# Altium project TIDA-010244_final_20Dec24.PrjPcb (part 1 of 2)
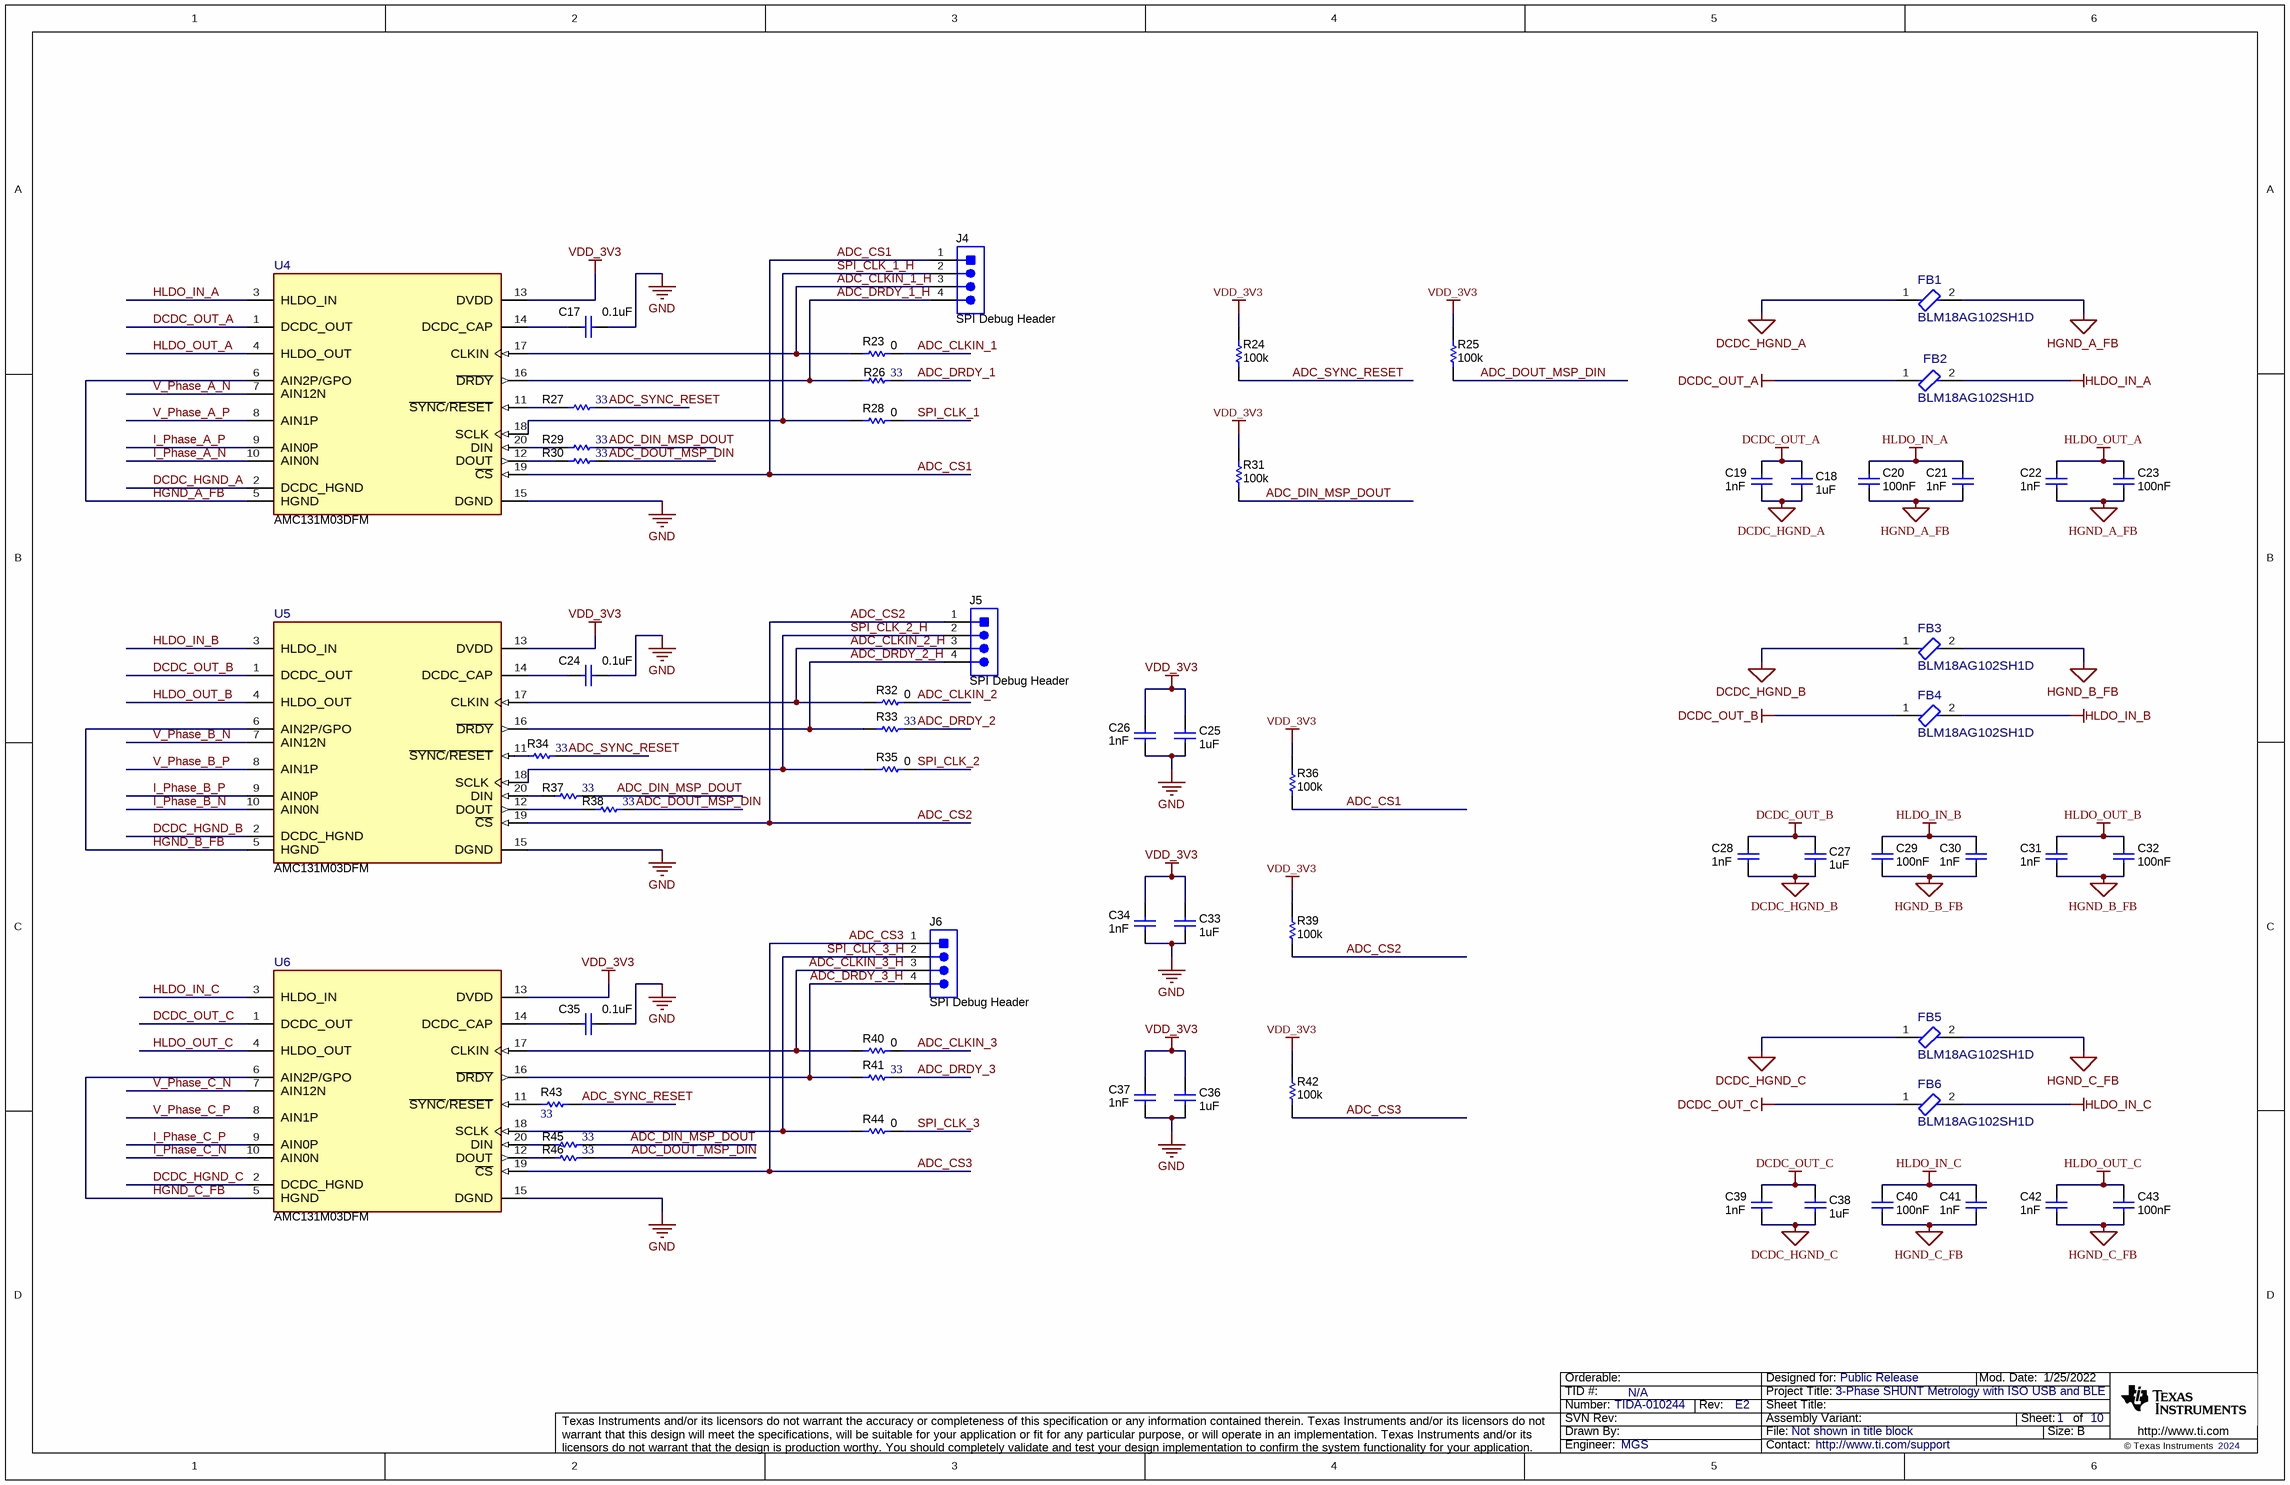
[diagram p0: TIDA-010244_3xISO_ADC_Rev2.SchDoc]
CopyrightYear: 2024; PCB_Layout: a0797195; PCB_Rev: E2; PRJ_Customer: Public Release; PRJ_Engineer: MGS; PRJ_Number: TIDA-010244; PRJ_Title: 3-Phase SHUNT Metrology with ISO USB and BLE; SCH_Rev: E2; TechSupport: http://www.ti.com/support; TID: N/A
9 sheets, 357 parts. Net scope: global (net labels, ports and power ports of the same name join across sheets).
Board file: TIDA-010244_Rev2_final.PcbDoc
Sheets:
  TIDA-010244_3xISO_ADC_Rev2.SchDoc
  TIDA-010244_Hardware.SchDoc
  TIDA-010244_MSPM0G_Rev2.SchDoc
  TIDA-010244_V_I_Filtering_FE_Rev2.SchDoc
  TIDA-010244_USB_and_Power.SchDoc
  TIDA-010244_BLE_Wireless.SchDoc
  TIDA-010244_XDS110_MCU.SchDoc
  TIDA-010244_Neutral_3DHall_Rev2.SchDoc
  TIDA-010244_BLE_Module_HY-2340.SchDoc

## Sheet TIDA-010244_3xISO_ADC_Rev2.SchDoc
size 431 x 279 mm; Date: Not shown in title block; ApprovedBy: Not shown in title block; CheckedBy: Not shown in title block; Author: Not shown in title block; CompanyName: Not shown in title block; Engineer: Not shown in title block; Organization: Not shown in title block; Address1: Not shown in title block; Address2: Not shown in title block; Address3: Not shown in title block; Address4: Not shown in title block; DocumentNumber: 2; Revision: Use project parameter SCH_Rev; SheetNumber: 1; SheetTotal: 10; PageSetup: Record=PageOptions¦CenterHorizontal=True¦CenterVertical=True¦PrintScale=1.00¦XCorrection=1.00¦YCorrection=1.00¦PrintKind=0¦BorderSize=5000000¦LeftOffset=0¦BottomOffset=0¦Orientation=2¦PaperLength=1000¦PaperWidth=1000¦Scale=100¦PaperSource=15¦PrintQuality=600¦MediaType=1¦DitherType=10¦PaperKind=Letter¦PrintScaleMode=1

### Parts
C17  value 0.1uF  [0603]  (hidden comment: C1608X7R1H104K080AA)
C18  ValueDisplayed: 1uF  [0603]  (hidden comment: C0603C105K3RACTU)
C19  Cap_F: 1nF  [0603]  (hidden comment: C0603C102K5RACTU)
C20  Cap_F: 100nF  [0603]  (hidden comment: C1608X7R1H104K080AA)
C21  Cap_F: 1nF  [0603]  (hidden comment: C0603C102K5RACTU)
C22  Cap_F: 1nF  [0603]  (hidden comment: C0603C102K5RACTU)
C23  Cap_F: 100nF  [0603]  (hidden comment: C1608X7R1H104K080AA)
C24  value 0.1uF  [0603]  (hidden comment: C1608X7R1H104K080AA)
C25  ValueDisplayed: 1uF  [0603]  (hidden comment: C0603C105K3RACTU)
C26  Cap_F: 1nF  [0603]  (hidden comment: C0603C102K5RACTU)
C27  ValueDisplayed: 1uF  [0603]  (hidden comment: C0603C105K3RACTU)
C28  Cap_F: 1nF  [0603]  (hidden comment: C0603C102K5RACTU)
C29  Cap_F: 100nF  [0603]  (hidden comment: C1608X7R1H104K080AA)
C30  Cap_F: 1nF  [0603]  (hidden comment: C0603C102K5RACTU)
C31  Cap_F: 1nF  [0603]  (hidden comment: C0603C102K5RACTU)
C32  Cap_F: 100nF  [0603]  (hidden comment: C1608X7R1H104K080AA)
C33  ValueDisplayed: 1uF  [0603]  (hidden comment: C0603C105K3RACTU)
C34  Cap_F: 1nF  [0603]  (hidden comment: C0603C102K5RACTU)
C35  value 0.1uF  [0603]  (hidden comment: C1608X7R1H104K080AA)
C36  ValueDisplayed: 1uF  [0603]  (hidden comment: C0603C105K3RACTU)
C37  Cap_F: 1nF  [0603]  (hidden comment: C0603C102K5RACTU)
C38  ValueDisplayed: 1uF  [0603]  (hidden comment: C0603C105K3RACTU)
C39  Cap_F: 1nF  [0603]  (hidden comment: C0603C102K5RACTU)
C40  Cap_F: 100nF  [0603]  (hidden comment: C1608X7R1H104K080AA)
C41  Cap_F: 1nF  [0603]  (hidden comment: C0603C102K5RACTU)
C42  Cap_F: 1nF  [0603]  (hidden comment: C0603C102K5RACTU)
C43  Cap_F: 100nF  [0603]  (hidden comment: C1608X7R1H104K080AA)
FB1  BLM18AG102SH1D  [FP-BLM18AG102SH1D_0603-MFG]
FB2  BLM18AG102SH1D  [FP-BLM18AG102SH1D_0603-MFG]
FB3  BLM18AG102SH1D  [FP-BLM18AG102SH1D_0603-MFG]
FB4  BLM18AG102SH1D  [FP-BLM18AG102SH1D_0603-MFG]
FB5  BLM18AG102SH1D  [FP-BLM18AG102SH1D_0603-MFG]
FB6  BLM18AG102SH1D  [FP-BLM18AG102SH1D_0603-MFG]
J4  SPI Debug Header  [WURTH_61300411121]
J5  SPI Debug Header  [WURTH_61300411121]
J6  SPI Debug Header  [WURTH_61300411121]
R23  ValueDisplayed: 0  [0603]  (hidden comment: ERJ-3GEY0R00V)
R24  ValueDisplayed: 100k  [0603]  (hidden comment: CRCW0603100KFKEA)
R25  ValueDisplayed: 100k  [0603]  (hidden comment: CRCW0603100KFKEA)
R26  ValueDisplayed: 33  [0603]  (hidden comment: CRCW060333R0JNEA)
R27  ValueDisplayed: 33  [0603]  (hidden comment: CRCW060333R0JNEA)
R28  ValueDisplayed: 0  [0603]  (hidden comment: ERJ-3GEY0R00V)
R29  ValueDisplayed: 33  [0603]  (hidden comment: CRCW060333R0JNEA)
R30  ValueDisplayed: 33  [0603]  (hidden comment: CRCW060333R0JNEA)
R31  ValueDisplayed: 100k  [0603]  (hidden comment: CRCW0603100KFKEA)
R32  ValueDisplayed: 0  [0603]  (hidden comment: ERJ-3GEY0R00V)
R33  ValueDisplayed: 33  [0603]  (hidden comment: CRCW060333R0JNEA)
R34  ValueDisplayed: 33  [0603]  (hidden comment: CRCW060333R0JNEA)
R35  ValueDisplayed: 0  [0603]  (hidden comment: ERJ-3GEY0R00V)
R36  ValueDisplayed: 100k  [0603]  (hidden comment: CRCW0603100KFKEA)
R37  ValueDisplayed: 33  [0603]  (hidden comment: CRCW060333R0JNEA)
R38  ValueDisplayed: 33  [0603]  (hidden comment: CRCW060333R0JNEA)
R39  ValueDisplayed: 100k  [0603]  (hidden comment: CRCW0603100KFKEA)
R40  ValueDisplayed: 0  [0603]  (hidden comment: ERJ-3GEY0R00V)
R41  ValueDisplayed: 33  [0603]  (hidden comment: CRCW060333R0JNEA)
R42  ValueDisplayed: 100k  [0603]  (hidden comment: CRCW0603100KFKEA)
R43  ValueDisplayed: 33  [0603]  (hidden comment: CRCW060333R0JNEA)
R44  ValueDisplayed: 0  [0603]  (hidden comment: ERJ-3GEY0R00V)
R45  ValueDisplayed: 33  [0603]  (hidden comment: CRCW060333R0JNEA)
R46  ValueDisplayed: 33  [0603]  (hidden comment: CRCW060333R0JNEA)
U4  AMC131M03DFM  [DFM0020A-MFG]
U5  AMC131M03DFM  [DFM0020A-MFG]
U6  AMC131M03DFM  [DFM0020A-MFG]

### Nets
DCDC_HGND_A: C18.1 C19.2 FB1.1 U4.2(DCDC_HGND)
DCDC_HGND_B: C27.1 C28.2 FB3.1 U5.2(DCDC_HGND)
DCDC_HGND_C: C38.1 C39.2 FB5.1 U6.2(DCDC_HGND)
DCDC_OUT_A: C18.2 C19.1 FB2.1 U4.1(DCDC_OUT)
DCDC_OUT_B: C27.2 C28.1 FB4.1 U5.1(DCDC_OUT)
DCDC_OUT_C: C38.2 C39.1 FB6.1 U6.1(DCDC_OUT)
GND: C17.2 C24.2 C25.1 C26.2 C33.1 C34.2 C35.2 C36.1 C37.2 U4.15(DGND) U5.15(DGND) U6.15(DGND)
HGND_A_FB: C20.2 C21.2 C22.2 C23.2 FB1.2 U4.5(HGND) U4.6(AIN2P/GPO)
HGND_B_FB: C29.2 C30.2 C31.2 C32.2 FB3.2 U5.5(HGND) U5.6(AIN2P/GPO)
HGND_C_FB: C40.2 C41.2 C42.2 C43.2 FB5.2 U6.5(HGND) U6.6(AIN2P/GPO)
HLDO_IN_A: C20.1 C21.1 FB2.2 U4.3(HLDO_IN)
HLDO_IN_B: C29.1 C30.1 FB4.2 U5.3(HLDO_IN)
HLDO_IN_C: C40.1 C41.1 FB6.2 U6.3(HLDO_IN)
HLDO_OUT_A: C22.1 C23.1 U4.4(HLDO_OUT)
HLDO_OUT_B: C31.1 C32.1 U5.4(HLDO_OUT)
HLDO_OUT_C: C42.1 C43.1 U6.4(HLDO_OUT)
VDD_3V3: C25.2 C26.1 C33.2 C34.1 C36.2 C37.1 R24.2 R25.2 R31.2 R36.2 R39.2 R42.2 U4.13(DVDD) U5.13(DVDD) U6.13(DVDD)
ADC_CLKIN_1: R23.2
ADC_CLKIN_1_H: J4.3 R23.1 U4.17(CLKIN)
ADC_CLKIN_2: R32.2
ADC_CLKIN_2_H: J5.3 R32.1 U5.17(CLKIN)
ADC_CLKIN_3: R40.2
ADC_CLKIN_3_H: J6.3 R40.1 U6.17(CLKIN)
ADC_CS1: J4.1 R36.1 U4.19(~{CS})
ADC_CS2: J5.1 R39.1 U5.19(~{CS})
ADC_CS3: J6.1 R42.1 U6.19(~{CS})
ADC_DIN_MSP_DOUT: R29.2 R31.1 R37.2 R45.2
ADC_DOUT_MSP_DIN: R25.1 R30.2 R38.2 R46.2
ADC_DRDY_1: R26.2
ADC_DRDY_1_H: J4.4 R26.1 U4.16(~{DRDY})
ADC_DRDY_2: R33.2
ADC_DRDY_2_H: J5.4 R33.1 U5.16(~{DRDY})
ADC_DRDY_3: R41.2
ADC_DRDY_3_H: J6.4 R41.1 U6.16(~{DRDY})
ADC_SYNC_RESET: R24.1 R27.2 R34.2 R43.2
I_Phase_A_N: U4.10(AIN0N)
I_Phase_A_P: U4.9(AIN0P)
I_Phase_B_N: U5.10(AIN0N)
I_Phase_B_P: U5.9(AIN0P)
I_Phase_C_N: U6.10(AIN0N)
I_Phase_C_P: U6.9(AIN0P)
SPI_CLK_1: R28.2
SPI_CLK_1_H: J4.2 R28.1 U4.18(SCLK)
SPI_CLK_2: R35.2
SPI_CLK_2_H: J5.2 R35.1 U5.18(SCLK)
SPI_CLK_3: R44.2
SPI_CLK_3_H: J6.2 R44.1 U6.18(SCLK)
V_Phase_A_N: U4.7(AIN12N)
V_Phase_A_P: U4.8(AIN1P)
V_Phase_B_N: U5.7(AIN12N)
V_Phase_B_P: U5.8(AIN1P)
V_Phase_C_N: U6.7(AIN12N)
V_Phase_C_P: U6.8(AIN1P)
NetC17_1: C17.1 U4.14(DCDC_CAP)
NetC24_1: C24.1 U5.14(DCDC_CAP)
NetC35_1: C35.1 U6.14(DCDC_CAP)
NetR27_1: R27.1 U4.11(~{SYNC}/~{RESET})
NetR29_1: R29.1 U4.20(DIN)
NetR30_1: R30.1 U4.12(DOUT)
NetR34_1: R34.1 U5.11(~{SYNC}/~{RESET})
NetR37_1: R37.1 U5.20(DIN)
NetR38_1: R38.1 U5.12(DOUT)
NetR43_1: R43.1 U6.11(~{SYNC}/~{RESET})
NetR45_1: R45.1 U6.20(DIN)
NetR46_1: R46.1 U6.12(DOUT)

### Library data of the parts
C17 C24 C35 = CMP-0007044-5: CAP, CERM, 0.1 uF, 50 V, +/- 10%, X7R, 0603; Manufacturer: TDK; TaMin_C: -55°C; ESR_ohm: 29.6m; Polarized: N; SizeAreaWB_mm2: 4.68; Value1: 0.0296 ohm; U/M: EA; TaMax_C: 125°C; SizeZ_mm: 1; SizeX_mm: 1.6; SizeY_mm: 0.8; Value2: 50V; SizeArea_mm2: 1.28; IRMS_A: 971.99mA; AEC Category: Q200
C18 C25 C27 C33 C36 C38 = CMP-0006867-4: CAP, CERM, 1 uF, 25 V, +/- 10%, X7R, 0603; Manufacturer: Kemet; TaMin_C: -55°C; Polarized: N; SizeAreaWB_mm2: 4.68; Value1: Unknown; U/M: EA; Value: 1uF; TaMax_C: 125°C; SizeZ_mm: 1; SizeX_mm: 1.6; SizeY_mm: 0.8; Value2: 25V; SizeArea_mm2: 1.28; CompType: Capacitor; Cap_F: 1µF; AEC Category: Q200
C19 C21 C22 C26 C28 C30 C31 C34 C37 C39 C41 C42 = CMP-0006847-4: CAP, CERM, 1000 pF, 50 V, +/- 10%, X7R, 0603; Manufacturer: Kemet; TaMin_C: -55°C; Polarized: N; SizeAreaWB_mm2: 4.68; Value1: Unknown; U/M: EA; Value: 1000pF; TaMax_C: 125°C; SizeZ_mm: 1; SizeX_mm: 1.6; SizeY_mm: 0.8; Value2: 50V; SizeArea_mm2: 1.28; AEC Category: Q200
C20 C23 C29 C32 C40 C43 = CMP-0007044-5: CAP, CERM, 0.1 uF, 50 V, +/- 10%, X7R, 0603; Manufacturer: TDK; TaMin_C: -55°C; ESR_ohm: 29.6m; Polarized: N; SizeAreaWB_mm2: 4.68; Value1: 0.0296 ohm; U/M: EA; Value: 0.1uF; TaMax_C: 125°C; SizeZ_mm: 1; SizeX_mm: 1.6; SizeY_mm: 0.8; Value2: 50V; SizeArea_mm2: 1.28; IRMS_A: 971.99mA; AEC Category: Q200
FB1-FB6 = CMP-0092964-1: Chip Ferrite Bead, 0603, 1000Ω @ 100MHz, 0.5Ω, 25%, 450mA; Manufacturer: Murata; SizeZ_mm: 0.95mm; AEC Qualified: Yes; DCR_ohm: 0.5; AEC Grade: Grade 1
J4-J6 = CMP-0054798-2: Header, 2.54 mm, 4x1, Gold, TH; Manufacturer: Wurth Elektronik; PartNumber: 61300411121; Pitch_mm: 2.54; Gender: Male; Row_Count: 1; Cert_UL: Y; Shrouded: N
R23 R28 R32 R35 R40 R44 = CMP-0025874-4: RES, 0, 5%, 0.1 W, AEC-Q200 Grade 0, 0603; Manufacturer: Panasonic; Power_W: 100mW; TempCo: 600 ppm/C; Value_Code: 0000; Value: 0; EIA_Code: E24; SizeX_mm: 1.6; SizeY_mm: 0.8; SizeZ_mm: 1; Value2: 0.1W; SizeArea_mm2: 1.28; AEC Qualified: Y; VDC_V: 50V; AEC Category: Q200; SizeAreaWB_mm2: 4.68
R24 R25 R31 R36 R39 R42 = CMP-0021990-4: RES, 100 k, 1%, 0.1 W, AEC-Q200 Grade 0, 0603; Manufacturer: Vishay-Dale; Power_W: 100mW; TempCo: 100 ppm/C; Value: 100k; EIA_Code: E96; SizeX_mm: 1.6; SizeY_mm: 0.8; SizeZ_mm: 1; Value2: 0.1W; SizeArea_mm2: 1.28; AEC Qualified: Y; VDC_V: 75V; AEC Category: Q200; AEC Grade: 0
R26 R27 R29 R30 R33 R34 R37 R38 R41 R43 R45 R46 = CMP-0025787-4: RES, 33, 5%, 0.1 W, AEC-Q200 Grade 0, 0603; Manufacturer: Vishay-Dale; Power_W: 100mW; TempCo: 200 ppm/C; Value_Code: 33R0; Value: 33; EIA_Code: E24; SizeX_mm: 1.6; SizeY_mm: 0.8; SizeZ_mm: 1; Value2: 0.1W; SizeArea_mm2: 1.28; AEC Qualified: Y; VDC_V: 75V; AEC Category: Q200; AEC Grade: 0
U4-U6 = CMP-0093943-1: 3-Channel, Simultaneously-Sampling, 24-Bit, Reinforced Isolated DeltaSigma ADC With Integrated DC/DC Converter; Manufacturer: Texas Instruments; Interface: SPI; TaMax_C: +125°C; Standoff Height: 0.1mm; Resolution: 24bits; Max Supply Voltage: 5.5V; Data Polarity: Differential; Min Supply Voltage: 3V; TJmax_C: +150°C; Number Of Channels: 3; Sampling Rate: 32ksps; TaMin_C: -40°C; SizeZ_mm: 3.55mm; AEC Qualified: No

## Sheet TIDA-010244_Hardware.SchDoc
size 431 x 279 mm; Date: Not shown in title block; ApprovedBy: Not shown in title block; CheckedBy: Not shown in title block; Author: Not shown in title block; CompanyName: Not shown in title block; Engineer: Not shown in title block; Organization: Not shown in title block; Address1: Not shown in title block; Address2: Not shown in title block; Address3: Not shown in title block; Address4: Not shown in title block; DocumentNumber: 3; Revision: Use project parameter SCH_Rev; SheetNumber: 2; SheetTotal: 9; PageSetup: Record=PageOptions¦CenterHorizontal=True¦CenterVertical=True¦PrintScale=1.00¦XCorrection=1.00¦YCorrection=1.00¦PrintKind=0¦BorderSize=5000000¦LeftOffset=0¦BottomOffset=0¦Orientation=2¦PaperLength=1000¦PaperWidth=1000¦Scale=100¦PaperSource=15¦PrintQuality=600¦MediaType=1¦DitherType=10¦PaperKind=Letter¦PrintScaleMode=1
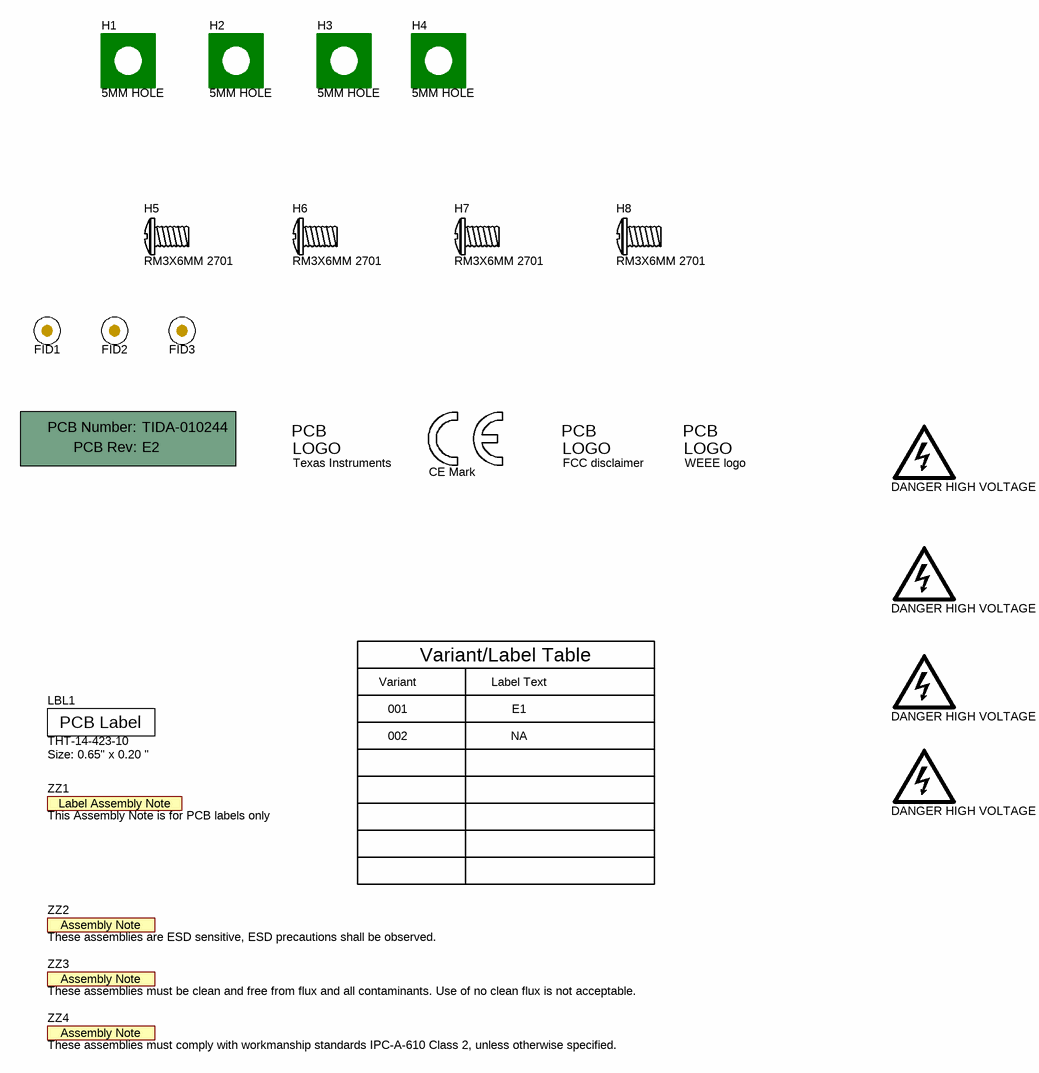
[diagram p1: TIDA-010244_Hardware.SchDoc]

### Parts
!PCB1  Printed Circuit Board  (value not drawn)  (mechanical)
FID1  Fiducial  [Fiducial10-20]  (value not drawn)
FID2  Fiducial  [Fiducial10-20]  (value not drawn)
FID3  Fiducial  [Fiducial10-20]  (value not drawn)
H1  5MM HOLE  [5MM_HOLE]
H2  5MM HOLE  [5MM_HOLE]
H3  5MM HOLE  [5MM_HOLE]
H4  5MM HOLE  [5MM_HOLE]
H5  RM3X6MM 2701  (mechanical)
H6  RM3X6MM 2701  (mechanical)
H7  RM3X6MM 2701  (mechanical)
H8  RM3X6MM 2701  (mechanical)
LBL1  THT-14-423-10  Note: Size: 0.65" x 0.20 "  [Label_650x200]
Logo1  Texas Instruments  [TI_Stacked_Overlay_Small]  (no BOM)
Logo2  CE Mark  [CE_Mark_5mm]  (no BOM)
Logo3  FCC disclaimer  [FCC_disclaimer]  (no BOM)
Logo4  WEEE logo  [WEEE_Minimum]  (no BOM)
LOGO5  DANGER HIGH VOLTAGE  [IEC_HighVoltage_Medium]  (no BOM)
LOGO6  DANGER HIGH VOLTAGE  [IEC_HighVoltage_Medium]  (no BOM)
LOGO7  DANGER HIGH VOLTAGE  [IEC_HighVoltage_Medium]  (no BOM)
LOGO8  DANGER HIGH VOLTAGE  [IEC_HighVoltage_Medium]  (no BOM)
ZZ1  This Assembly Note is for PCB labels only  [AssemblyNoteLabel]  (no BOM)
ZZ2  These assemblies are ESD sensitive, ESD precautions shall be observed.  [AssemblyNote]  (no BOM)
ZZ3  These assemblies must be clean and free from flux and all contaminants. Use of no clean flux is not acceptable.  [AssemblyNote]  (no BOM)
ZZ4  These assemblies must comply with workmanship standards IPC-A-610 Class 2, unless otherwise specified.  [AssemblyNote]  (no BOM)

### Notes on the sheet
- Variant
- Variant/Label Table
- Label Text
- 001
- 002
- E1
- NA

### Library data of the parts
!PCB1 = CMP-0003618-2: Manufacturer: Any; PartNumber: TIDA-010244
FID1-FID3 = CMP-0077181-1: Fiducial mark.  There is nothing to buy or mount.
H1-H4 = CMP-0079337-1: 5 mm PCB Hole; Manufacturer: Any; CompType: Pad
H5-H8 = CMP-0077936-1: MACHINE SCREW PAN PHILLIPS M3; Manufacturer: APM HEXSEAL; CompType: Standoff
LBL1 = CMP-0003625-1: Thermal Transfer Printable Labels, 0.650" W x 0.200" H - 10,000 per roll; Manufacturer: Brady; CompType: Label
Logo1 = CMP-0074838-1: Texas Instrument Corporate Signature; SymbolCreator: a0412235; Lib Reference: TI_Logo; Library Reference: Logo
Logo2 = CMP-0074844-1: SymbolCreator: a0412235
Logo3 = CMP-0074847-1: FCC_disclaimer; Library Reference: Logo
Logo4 = CMP-0074769-1
LOGO5-LOGO8 = CMP-0074835-1: IEC 61010-1 High Voltage Warning; SymbolCreator: a0412235
ZZ1 = CMP-0003616-3
ZZ2 = CMP-0077236-1
ZZ3 = CMP-0077237-1
ZZ4 = CMP-0077238-1

## Sheet TIDA-010244_MSPM0G_Rev2.SchDoc
size A2; Date: Not shown in title block; ApprovedBy: Not shown in title block; CheckedBy: Not shown in title block; Author: Not shown in title block; CompanyName: Not shown in title block; Engineer: Not shown in title block; Organization: Not shown in title block; Address1: Not shown in title block; Address2: Not shown in title block; Address3: Not shown in title block; Address4: Not shown in title block; DocumentNumber: 1; Revision: Use project parameter SCH_Rev; SheetNumber: 3; SheetTotal: 9; PageSetup: Record=PageOptions¦CenterHorizontal=True¦CenterVertical=True¦PrintScale=0.69¦XCorrection=1.00¦YCorrection=1.00¦PrintKind=0¦BorderSize=5000000¦LeftOffset=0¦BottomOffset=0¦Orientation=2¦PaperLength=1000¦PaperWidth=1000¦Scale=100¦PaperSource=15¦PrintQuality=600¦MediaType=1¦DitherType=10¦PaperKind=Letter¦PrintScaleMode=1
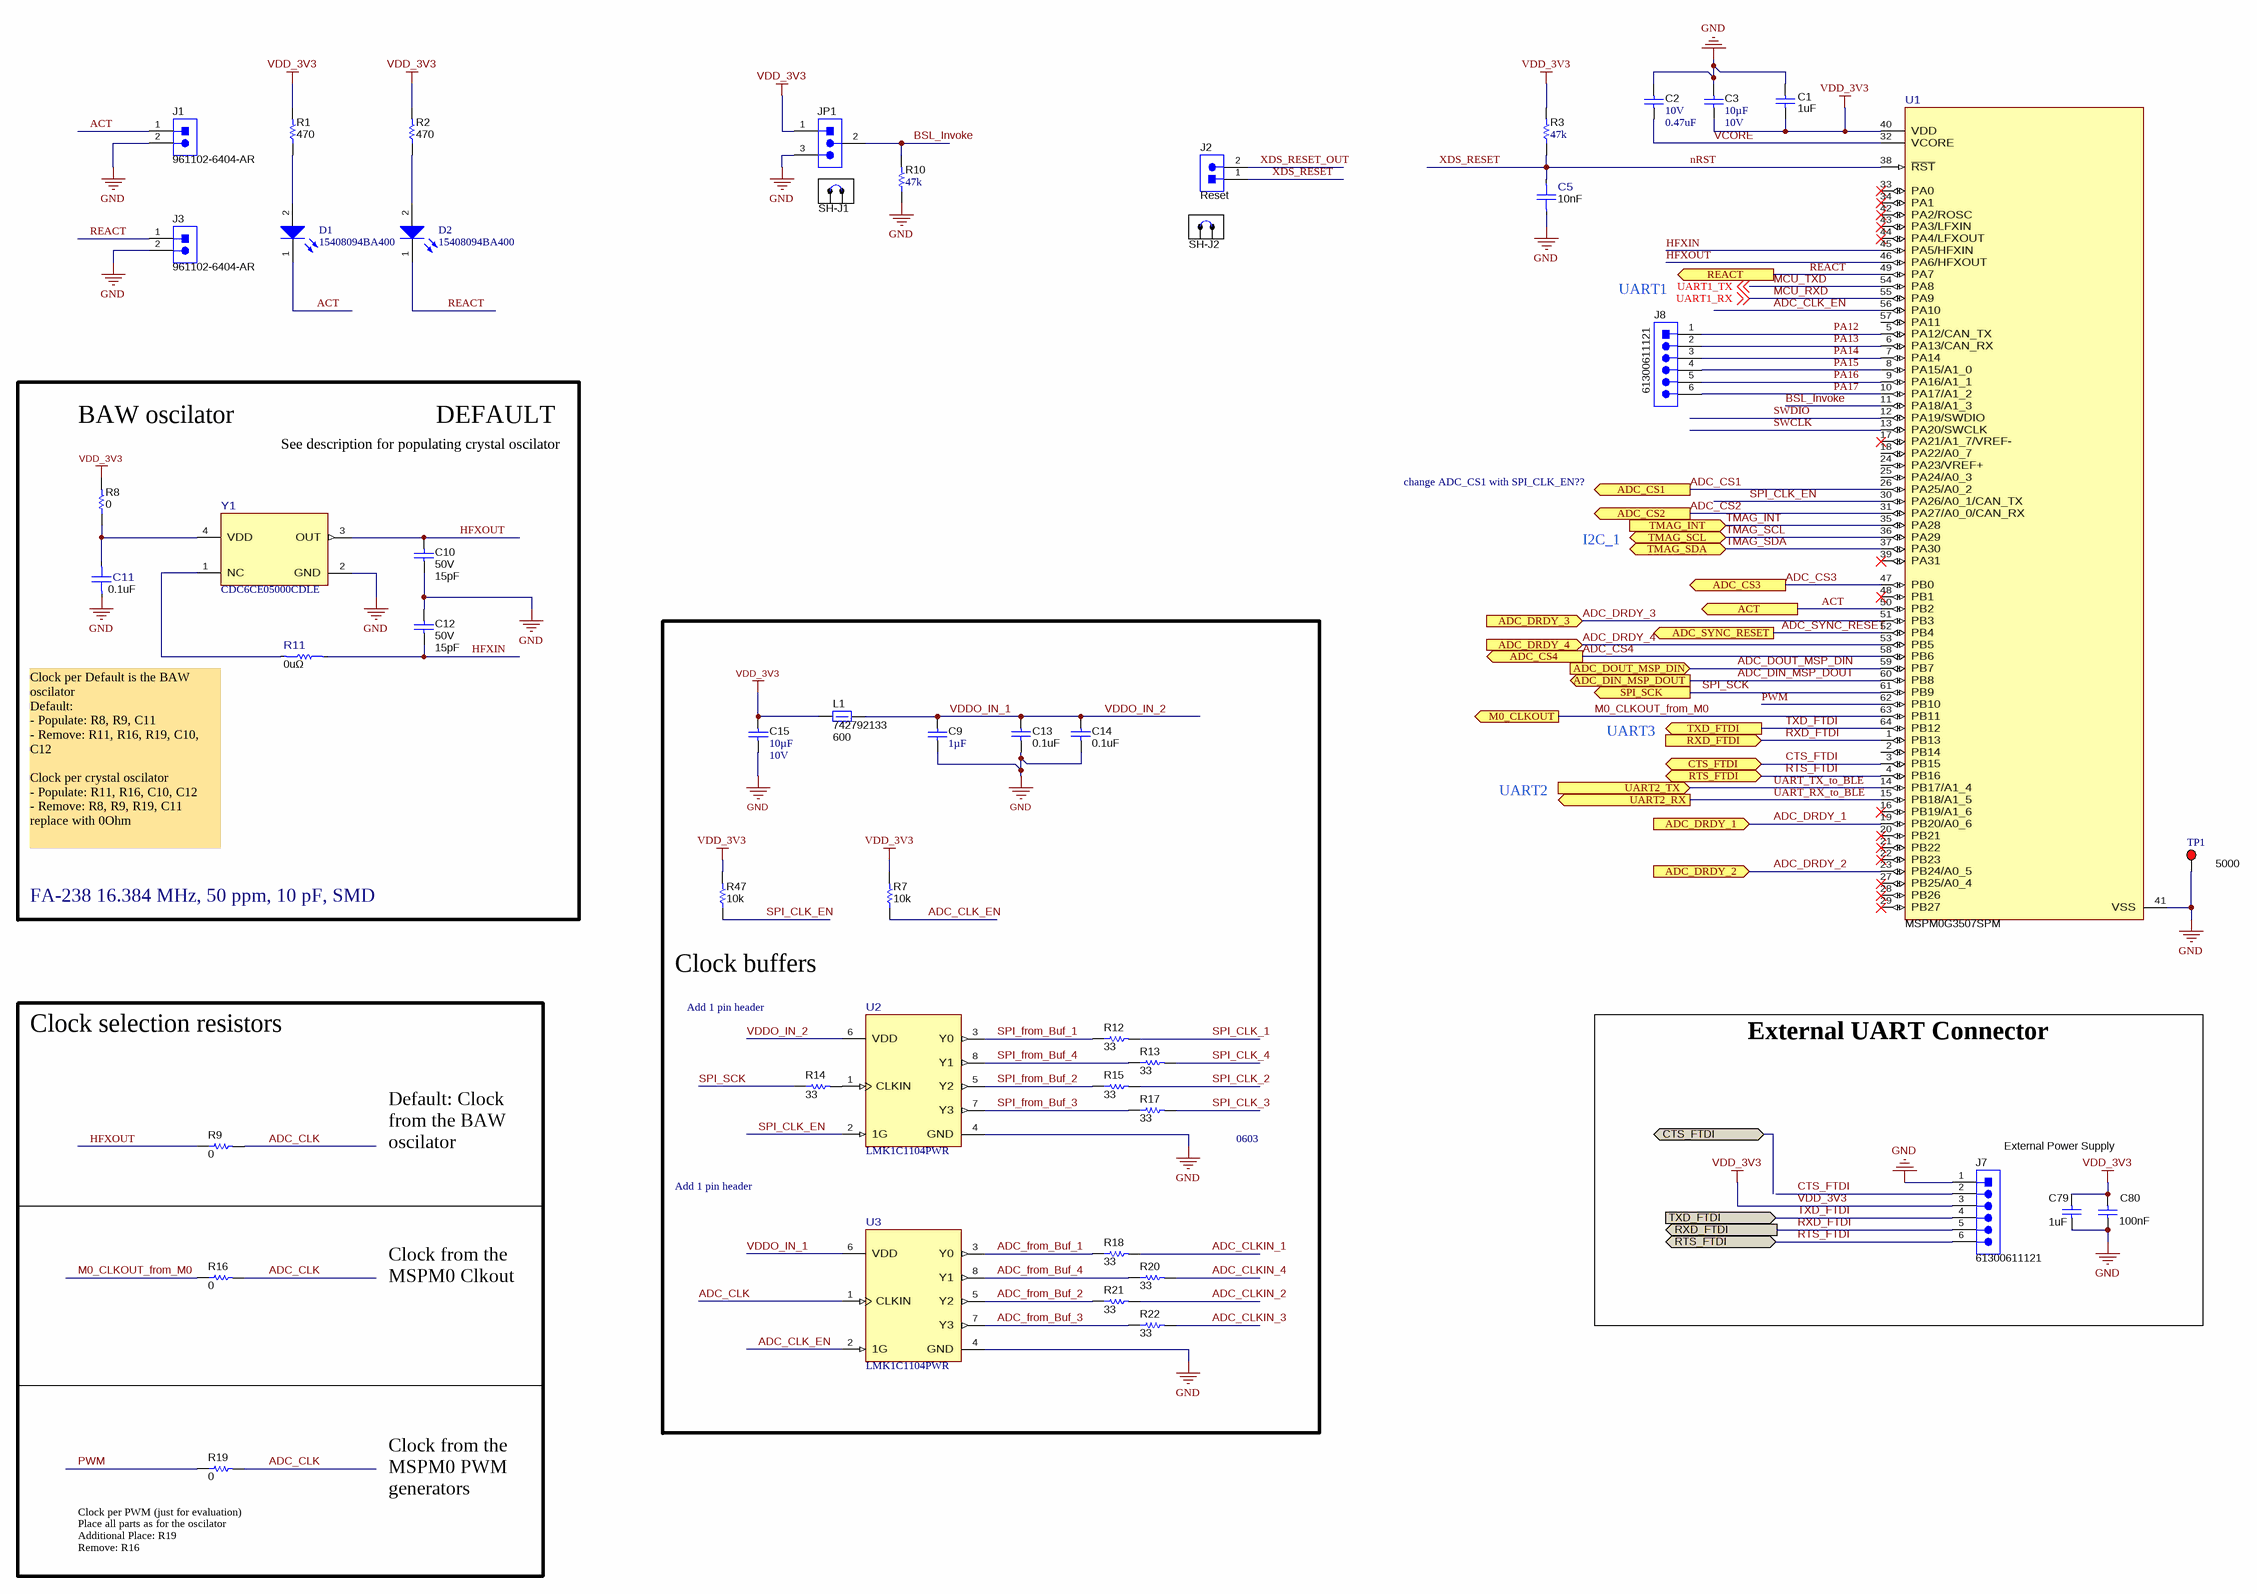
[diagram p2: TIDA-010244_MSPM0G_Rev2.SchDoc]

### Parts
C1  ValueDisplayed: 1uF  [0603]  (hidden comment: C0603C105K3RACTU)
C2  VDC_V: 10V  ValueDisplayed: 0.47uF  [0603]  (hidden comment: GRM188R61A474KA61D)
C3  ValueDisplayed: 10µF  VDC_V: 10V  [0603]  (hidden comment: GRM188R61A106KAALD)
C5  ValueDisplayed: 10nF  [FP-885012205050_0402-MFG]  (hidden comment: 885012205050)
C9  Cap_F: 1µF  [0603]  (hidden comment: CGA3E1X7R1C105K080AC)
C10  VDC_V: 50V  ValueDisplayed: 15pF  [0402]  (hidden comment: GRM1555C1H150JA01D)
C11  ValueDisplayed: 0.1uF  [FP-885012205018_0402-MFG]  (hidden comment: 885012205018)
C12  VDC_V: 50V  ValueDisplayed: 15pF  [0402]  (hidden comment: GRM1555C1H150JA01D)
C13  value 0.1uF  [0603]  (hidden comment: C1608X7R1H104K080AA)
C14  value 0.1uF  [0603]  (hidden comment: C1608X7R1H104K080AA)
C15  ValueDisplayed: 10µF  VDC_V: 10V  [0603]  (hidden comment: GRM188R61A106KAALD)
C79  ValueDisplayed: 1uF  [0603]  (hidden comment: C0603C105K3RACTU)
C80  Cap_F: 100nF  [0603]  (hidden comment: C0603X104K3RACTU)
D1  15408094BA400  [WL-SICW_0805_L2W1.3H0.8]
D2  15408094BA400  [WL-SICW_0805_L2W1.3H0.8]
J1  961102-6404-AR  [3M_961102-6404-AR]
J2  Reset  [3M_961102-6404-AR]
J3  961102-6404-AR  [3M_961102-6404-AR]
J7  61300611121  [WURTH_61300611121]
J8  61300611121  [WURTH_61300611121]
JP1  TSW-103-07-G-S  [TSW-103-07-G-S]  (value not drawn)
L1  742792133  ZTyp@100MHz_Ohm: 600  [1206]
R1  ValueDisplayed: 470  [0402]  (hidden comment: RC0402FR-07470RL)
R2  ValueDisplayed: 470  [0402]  (hidden comment: RC0402FR-07470RL)
R3  ValueDisplayed: 47k  [0402]  (hidden comment: CRCW040247K0JNED)
R7  ValueDisplayed: 10k  [0402]  (hidden comment: CRCW040210K0JNED)
R8  ValueDisplayed: 0  [0402]  (hidden comment: RC0402JR-070RL)
R9  ValueDisplayed: 0  [0603]  (hidden comment: ERJ-3GEY0R00V)
R10  ValueDisplayed: 47k  [0402]  (hidden comment: CRCW040247K0JNED)
R11  value 0uΩ  [FP-CR0402-10W-000T_0402-MFG]  (hidden comment: CR0402-10W-000T)
R12  ValueDisplayed: 33  [0402]  (hidden comment: CRCW040233R0JNED)
R13  ValueDisplayed: 33  [0402]  (hidden comment: CRCW040233R0JNED)
R14  ValueDisplayed: 33  [0402]  (hidden comment: CRCW040233R0JNED)
R15  ValueDisplayed: 33  [0402]  (hidden comment: CRCW040233R0JNED)
R16  ValueDisplayed: 0  [0603]  (hidden comment: ERJ-3GEY0R00V)
R17  ValueDisplayed: 33  [0402]  (hidden comment: CRCW040233R0JNED)
R18  ValueDisplayed: 33  [0402]  (hidden comment: CRCW040233R0JNED)
R19  ValueDisplayed: 0  [0603]  (hidden comment: ERJ-3GEY0R00V)
R20  ValueDisplayed: 33  [0402]  (hidden comment: CRCW040233R0JNED)
R21  ValueDisplayed: 33  [0402]  (hidden comment: CRCW040233R0JNED)
R22  ValueDisplayed: 33  [0402]  (hidden comment: CRCW040233R0JNED)
R47  ValueDisplayed: 10k  [0402]  (hidden comment: CRCW040210K0JNED)
SH-J1  881545-2  [TE_881545-2]  (value not drawn)  (mechanical)
SH-J2  881545-2  [TE_881545-2]  (value not drawn)  (mechanical)
TP1  5000  [Keystone5000]
U1  MSPM0G3507SPM  [PM0064A-MFG]
U2  LMK1C1104PWR  [PW0008A-MFG]
U3  LMK1C1104PWR  [PW0008A-MFG]
Y1  CDC6CE05000CDLE  [DLE0004A-MFG]

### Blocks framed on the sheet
Clock buffers: C9 C13-C15 L1 R7 R12-R15 R17 R18 R20-R22 R47 U2 U3
Clock selection resistors: R9 R16 R19

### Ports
ACT (out), ADC_CS1 (out), ADC_CS2 (out), ADC_CS3 (out), ADC_CS4 (out), ADC_DIN_MSP_DOUT (out), ADC_DOUT_MSP_DIN (in), ADC_DRDY_1 (in), ADC_DRDY_2 (in), ADC_DRDY_3 (in), ADC_DRDY_4 (in), ADC_SYNC_RESET (out), CTS_FTDI (bidir), M0_CLKOUT (out), REACT (out), RTS_FTDI (bidir), RXD_FTDI (in), RXD_FTDI (out), SPI_SCK (out), TMAG_INT (in), TMAG_SCL (bidir), TMAG_SDA (bidir), TXD_FTDI (in), TXD_FTDI (out), UART2_RX (out), UART2_TX (in)

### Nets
GND: C1.2 C2.1 C3.1 C5.1 C9.2 C10.2 C11.1 C12.1 C13.1 C14.1 C15.2 C79.1 C80.2 J1.2 J3.2 J7.1 JP1.3 R10.1 TP1.1 U1.41(VSS) U2.4(GND) U3.4(GND) Y1.2(GND)
VDD_3V3: C1.1 C3.2 C15.1 C79.2 C80.1 J7.3 JP1.1 L1.1 R1.2 R2.2 R3.2 R7.2 R8.2 R47.2 U1.40(VDD)
ACT: D1.1(K) J1.1 U1.50(PB2) ; port ACT
ADC_CLK: R9.2 R16.2 R19.2 U3.1(CLKIN)
ADC_CLK_EN: R7.1 U1.56(PA10) U3.2(1G)
ADC_CLKIN_1: R18.2
ADC_CLKIN_2: R21.2
ADC_CLKIN_3: R22.2
ADC_CLKIN_4: R20.2
ADC_CS1: U1.26(PA25/A0_2) ; port ADC_CS1
ADC_CS2: U1.31(PA27/A0_0/CAN_RX) ; port ADC_CS2
ADC_CS3: U1.47(PB0) ; port ADC_CS3
ADC_CS4: U1.58(PB6) ; port ADC_CS4
ADC_DIN_MSP_DOUT: U1.60(PB8) ; port ADC_DIN_MSP_DOUT
ADC_DOUT_MSP_DIN: U1.59(PB7) ; port ADC_DOUT_MSP_DIN
ADC_DRDY_1: U1.19(PB20/A0_6) ; port ADC_DRDY_1
ADC_DRDY_2: U1.23(PB24/A0_5) ; port ADC_DRDY_2
ADC_DRDY_3: U1.51(PB3) ; port ADC_DRDY_3
ADC_DRDY_4: U1.53(PB5) ; port ADC_DRDY_4
ADC_from_Buf_1: R18.1 U3.3(Y0)
ADC_from_Buf_2: R21.1 U3.5(Y2)
ADC_from_Buf_3: R22.1 U3.7(Y3)
ADC_from_Buf_4: R20.1 U3.8(Y1)
ADC_SYNC_RESET: U1.52(PB4) ; port ADC_SYNC_RESET
BSL_Invoke: JP1.2 R10.2 U1.11(PA18/A1_3)
CTS_FTDI: J7.2 U1.3(PB15) ; port CTS_FTDI
HFXIN: C12.2 R11.2 U1.45(PA5/HFXIN)
HFXOUT: C10.1 R9.1 U1.46(PA6/HFXOUT) Y1.3(OUT)
M0_CLKOUT_from_M0: R16.1 U1.63(PB11) ; port M0_CLKOUT
MCU_RXD: U1.55(PA9) ; off-sheet UART1_RX  [also labelled UART1_RX]
MCU_TXD: U1.54(PA8) ; off-sheet UART1_TX  [also labelled UART1_TX]
nRST: C5.2 J2.1 R3.1 U1.38(~{RST})  [also labelled XDS_RESET]  [project net CC_RESET]
PA12: J8.1 U1.5(PA12/CAN_TX)
PA13: J8.2 U1.6(PA13/CAN_RX)
PA14: J8.3 U1.7(PA14)
PA15: J8.4 U1.8(PA15/A1_0)
PA16: J8.5 U1.9(PA16/A1_1)
PA17: J8.6 U1.10(PA17/A1_2)
PWM: R19.1 U1.62(PB10)
REACT: D2.1(K) J3.1 U1.49(PA7) ; port REACT
RTS_FTDI: J7.6 U1.4(PB16) ; port RTS_FTDI
RXD_FTDI: J7.5 U1.1(PB13) ; port RXD_FTDI
SPI_CLK_1: R12.2
SPI_CLK_2: R15.2
SPI_CLK_3: R17.2
SPI_CLK_4: R13.2
SPI_CLK_EN: R47.1 U1.30(PA26/A0_1/CAN_TX) U2.2(1G)
SPI_from_Buf_1: R12.1 U2.3(Y0)
SPI_from_Buf_2: R15.1 U2.5(Y2)
SPI_from_Buf_3: R17.1 U2.7(Y3)
SPI_from_Buf_4: R13.1 U2.8(Y1)
SPI_SCK: R14.1 U1.61(PB9) ; port SPI_SCK
SWCLK: U1.13(PA20/SWCLK)
SWDIO: U1.12(PA19/SWDIO)
TMAG_INT: U1.35(PA28) ; port TMAG_INT
TMAG_SCL: U1.36(PA29) ; port TMAG_SCL
TMAG_SDA: U1.37(PA30) ; port TMAG_SDA
TXD_FTDI: J7.4 U1.64(PB12) ; port TXD_FTDI
UART_RX_to_BLE: U1.15(PB18/A1_5) ; port UART2_RX
UART_TX_to_BLE: U1.14(PB17/A1_4) ; port UART2_TX
VCORE: C2.2 U1.32(VCORE)
VDDO_IN_1: C9.1 C13.2 C14.2 L1.2 U2.6(VDD) U3.6(VDD)  [also labelled VDDO_IN_2]
XDS_RESET_OUT: J2.2
NetC11_2: C11.2 R8.1 Y1.4(VDD)
NetD1_2: D1.2(A) R1.1
NetD2_2: D2.2(A) R2.1
NetR11_1: R11.1 Y1.1(NC)
NetR14_2: R14.2 U2.1(CLKIN)

Not connected (* = marked no-connect by the designer): U1 2(PB14) 16(PB19/A1_6)* 17(PA21/A1_7/VREF-)* 18(PA22/A0_7) 20(PB21)* 21(PB22)* 22(PB23)* 24(PA23/VREF+) 25(PA24/A0_3) 27(PB25/A0_4)* 28(PB26)* 29(PB27)* 33(PA0)* 34(PA1)* 39(PA31)* 42(PA2/ROSC)* 43(PA3/LFXIN)* 44(PA4/LFXOUT)* 48(PB1)* 57(PA11)

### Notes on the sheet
- (near J8) UART1
- BAW oscilator
- See description for populating crystal oscilator
- DEFAULT
- change ADC_CS1 with SPI_CLK_EN??
- I2C_1
- UART3
- UART2
- Clock per Default is the BAW oscilator
  Default:
  - Populate: R8, R9, C11
  - Remove: R11, R16, R19, C10, C12
  Clock per crystal oscilator
  - Populate: R11, R16, C10, C12
  - Remove: R8, R9, R19, C11 replace with 0Ohm
- FA-238 16.384 MHz, 50 ppm, 10 pF, SMD
- Add 1 pin header
- 0603
- External Power Supply
- Default: Clock from the BAW oscilator
- Clock from the MSPM0 Clkout
- External UART Connector
- (near R19) Clock per PWM (just for evaluation)
  Place all parts as for the oscilator
  Additional Place: R19
  Remove: R16
- Clock from the MSPM0 PWM generators

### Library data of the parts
C1 C79 = CMP-0006867-4: as C18 on sheet TIDA-010244_3xISO_ADC_Rev2
C2 = CMP-0007328-5: CAP, CERM, 0.47 uF, 10 V, +/- 10%, X5R, 0603; Manufacturer: MuRata; TaMin_C: -55°C; Polarized: N; SizeAreaWB_mm2: 4.68; Value1: Unknown; U/M: EA; Value: 0.47uF; TaMax_C: 85°C; SizeZ_mm: 1; SizeX_mm: 1.6; SizeY_mm: 0.8; SizeArea_mm2: 1.28; Cap_F: 470nF; AEC Category: Q200
C3 C15 = CMP-0086193-1: CAP, CERM, 10 µF, 10 V,+/- 10%, X5R, 0603; Manufacturer: MuRata; SizeArea_mm2: 1.28; SizeY_mm: 0.8; TaMax_C: 85°C; TaMin_C: -55°C; Polarized: N; SizeAreaWB_mm2: 4.68; SizeZ_mm: 1; SizeX_mm: 1.6; AEC Category: Q200; U/M: EA; Value: 10uF
C5 = CMP-0090363-1: 10000pF ±10% 25V Ceramic Capacitor X7R 0402 (1005 Metric); Manufacturer: Wurth Electronics; SizeZ_mm: 0.55mm; AEC Qualified: No; Value: 10nF; TempCo: 15%
C9 = CMP-0079607-1: CAP, CERM, 1 µF, 16 V,+/- 10%, X7R, AEC-Q200 Grade 1, 0603; Manufacturer: TDK; TaMin_C: -55°C; Polarized: N; SizeAreaWB_mm2: 4.68; U/M: EA; Value: 1uF; TaMax_C: 125°C; SizeZ_mm: 1; SizeX_mm: 1.6; SizeY_mm: 0.8; Value2: 16V; SizeArea_mm2: 1.28; AEC Qualified: Y; AEC Category: Q200
C10 C12 = CMP-0006420-2: CAP, CERM, 15 pF, 50 V, +/- 5%, C0G/NP0, 0402; Manufacturer: MuRata; TaMin_C: -55°C; Polarized: N; SizeAreaWB_mm2: 3; Value1: Unknown; U/M: EA; Value: 15pF; TaMax_C: 125°C; SizeZ_mm: 0.6; SizeX_mm: 1; SizeY_mm: 0.5; AEC Category: Q200
C11 = CMP-0090362-1: 0.1µF ±10% 10V Ceramic Capacitor X7R 0402 (1005 Metric); Manufacturer: Wurth Electronics; AEC Qualified: No; Value: 100nF; SizeZ_mm: 0.55mm; TempCo: 15%
C13 C14 = CMP-0007044-5: as C17 on sheet TIDA-010244_3xISO_ADC_Rev2
C80 = CMP-0006979-5: CAP, CERM, 0.1 uF, 25 V, +/- 10%, X7R, 0603; Manufacturer: Kemet; TaMin_C: -55°C; Polarized: N; SizeAreaWB_mm2: 4.68; Value1: Unknown; U/M: EA; Value: 0.1uF; TaMax_C: 125°C; SizeZ_mm: 1; SizeX_mm: 1.6; SizeY_mm: 0.8; Value2: 25V; SizeArea_mm2: 1.28; AEC Category: Q200
D1 D2 = CMP-03913-108242144-1: 15408094BA400 Ir Emitter, 940Nm, 0805 Rohs Compliant: Yes; Forward Current: 1A; Viewing Angle: 140°; Forward Voltage: 1.2V; Max Reverse Voltage (DC): 5V
J1 J3 = CMP-0075197-1: Header, 2.54mm, 2x1, TH; Manufacturer: 3M; CNHeader: True; Current_A: 2A; Green_Lifecycle: Active; Shrouded: N; Gender: Male; Green_REACh: Passed; Voltage_V: 1kV; Row_Count: 1; Pitch_mm: 2.54; ContactFinish: Gold; CT: False; Cert_UL: Y
J2 = CMP-0075197-1: Header, 2.54mm, 2x1, TH; Manufacturer: 3M; PartNumber: 961102-6404-AR; CNHeader: True; Current_A: 2A; Green_Lifecycle: Active; Shrouded: N; Gender: Male; Green_REACh: Passed; Voltage_V: 1kV; Row_Count: 1; Pitch_mm: 2.54; ContactFinish: Gold; CT: False; Cert_UL: Y
J7 J8 = CMP-0054801-2: Header, 2.54 mm, 6x1, Gold, TH; Manufacturer: Wurth Elektronik; Cert_UL: Y; Gender: Male; Row_Count: 1; Shrouded: N; Pitch_mm: 2.54
JP1 = CMP-0075407-2: Header, 100mil, 3x1, Gold, TH; Manufacturer: Samtec; Pitch_mm: 2.54; Cert_VDE: N; Gender: Male; Cert_CSA: Y; Voltage_V: 550V; Green_REACh: Passed; Current_A: 6.3A; Green_Lifecycle: Active; Row_Count: 1
L1 = CMP-0003124-1: Ferrite Bead, 600 ohm @ 100 MHz, 0.5 A, 1206; Manufacturer: Wurth Elektronik; Ztyp@1GHz_Ohm: 87.336; SizeAreaWB_mm2: 10.92; DCR_ohm: 0.3; Value1: 0.3 ohm; Value: 600 ohm; Imax_A: 500mA; SizeZ_mm: 1.35; SizeX_mm: 3.2; SizeY_mm: 1.6; Value2: 0.5A; SizeArea_mm2: 5.12
R1 R2 = CMP-0026736-1: RES, 470, 1%, 0.063 W, 0402; Manufacturer: Yageo America; Power_W: 63mW; TempCo: 100 ppm/C; Value_Code: 470R; U/M: EA; Value: 470; SizeX_mm: 1; SizeY_mm: 0.5; SizeZ_mm: 0.6; Value2: 0.063W; AEC Qualified: N; VDC_V: 50V; AEC Category: Q200
R3 R10 = CMP-0026935-3: RES, 47 k, 5%, 0.063 W, AEC-Q200 Grade 0, 0402; Manufacturer: Vishay-Dale; Power_W: 63mW; TempCo: 200 ppm/C; Value_Code: 47k0; Value: 47k; EIA_Code: E24; SizeX_mm: 1; SizeY_mm: 0.5; SizeZ_mm: 0.6; Value2: 0.063W; AEC Qualified: Y; VDC_V: 50V; AEC Category: Q200; AEC Grade: 0
R7 R47 = CMP-0026825-5: RES, 10 k, 5%, 0.063 W, AEC-Q200 Grade 0, 0402; Manufacturer: Vishay-Dale; Value: 10k; Value_Code: 10k0; Power_W: 63mW; Value2: 0.063W; VDC_V: 50V; TempCo: 200 ppm/C; SizeArea_mm2: 0.5; SizeX_mm: 1; SizeZ_mm: 0.6; EIA_Code: E24; AEC Category: Q200; AEC Qualified: Y; AEC Grade: 0
R8 = CMP-0027004-2: RES, 0, 5%, 0.063 W, 0402; Manufacturer: Yageo America; Power_W: 63mW; TempCo: 200 ppm/C; Value_Code: 0000; U/M: EA; Value: 0; EIA_Code: E24; SizeX_mm: 1; SizeY_mm: 0.5; SizeZ_mm: 0.6; Value2: 0.063W; VDC_V: 50V; AEC Category: Q200
R9 R16 R19 = CMP-0025874-4: as R23 on sheet TIDA-010244_3xISO_ADC_Rev2
R11 = CMP-0094948-1: 0 Ohms Jumper 0.1W, 1/10W Chip Resistor 0402 (1005 Metric) - Thick Film; Manufacturer: Venkel; AEC Qualified: No; VDC_V: 50V; SizeZ_mm: 0.4mm; Res_ohm: 0; Power_W: 100mW
R12 R13 R15 R17 R18 R20-R22 = CMP-0026908-1: RES, 33, 5%, 0.063 W, 0402; Manufacturer: Vishay-Dale; Power_W: 63mW; TempCo: 200 ppm/C; Value_Code: 33R0; U/M: EA; Value: 33; EIA_Code: E24; SizeX_mm: 1; SizeY_mm: 0.5; SizeZ_mm: 0.6; Value2: 0.063W; VDC_V: 50V; AEC Category: Q200
R14 = CMP-0026908-2: RES, 33, 5%, 0.063 W, 0402; Manufacturer: Vishay-Dale; Power_W: 63mW; TempCo: 200 ppm/C; Value_Code: 33R0; U/M: EA; Value: 33; EIA_Code: E24; SizeX_mm: 1; SizeY_mm: 0.5; SizeZ_mm: 0.6; Value2: 0.063W; VDC_V: 50V; AEC Category: Q200
SH-J1 SH-J2 = 881545-2: Shunt, 100mil, Gold plated, Black; Manufacturer: TE Connectivity
TP1 = CMP-0055137-1: Test Point, Miniature, Red, TH; Manufacturer: Keystone; CNHeader: FALSE; Green_Lifecycle: Active; Green_REACh: Passed; ContactFinish: Silver; CT: TRUE
U1 = CMP-0093960-1: Mixed-Signal Microcontrollers With CAN-FD Interface LQFP64; Manufacturer: Texas Instruments; Number Of I2C Channels: 2; Frequency_Fixed: 80MHz; Number Of Cores: 1; Number Of Pwm Channels: 14; Data Bus Width: 32bits; Standoff Height: 0.05mm; SizeZ_mm: 1.6mm; Number Of I/Os: 60; Memory Type: FLASH; Min Supply Voltage: 1.62V; Number Of Adc Channels: 16; Memory Size: 128KBytes; TJmax_C: +130°C; Number Of Uart Channels: 4; Number Of Timers/Counters: 7; Max Supply Voltage: 3.6V; TaMin_C: -40°C; Core Architecture: ARM Cortex-M0+; Interface: I2C,SPI,UART,CAN,LIN,IrDA,SMBus; Ram Size: 32KBytes; AEC Qualified: No; TaMax_C: +125°C
U2 U3 = CMP-0096980-1: 1.8-V, 2.5-V, and 3.3-V LVCMOS Clock Buffer Family; Manufacturer: Texas Instruments; Logic Function: Non-Inverting; TaMax_C: +125°C; TJmax_C: +150°C; Max Supply Voltage: 3.465V; Number Of Elements: 5; TaMin_C: -40°C; Nominal Supply Current: 25-33000uA; Number Of Outputs: 4; Number Of Inputs: 1; AEC Qualified: No; Min Supply Voltage: 1.71V; SizeZ_mm: 1.2mm; Standoff Height: 0.05mm; Propagation Delay: 1.5ns
Y1 = CMP-0094615-2: Crystal replacement: Ultra-low Power LVCMOS Oscillator 4-pin, VSON 3.2 x 2.5 x 0.9mm; Manufacturer: Texas Instruments; AEC Qualified: No; Standoff Height: 0mm; Min Supply Voltage: 2.375V; TaMin_C: -40°C; Load Capacitance: 15pF; Frequency Stability: 20ppm; AEC Category: Q200; Frequency_Fixed: 50MHz; CompType: IC; SizeZ_mm: 1mm; Max Supply Voltage: 3.465V; TJmax_C: +135°C; TaMax_C: +105°C; Max Supply Current: 4mA

## Sheet TIDA-010244_V_I_Filtering_FE_Rev2.SchDoc
size A3; Date: Not shown in title block; ApprovedBy: Not shown in title block; CheckedBy: Not shown in title block; Author: Not shown in title block; CompanyName: Not shown in title block; Engineer: Not shown in title block; Organization: Not shown in title block; Address1: Not shown in title block; Address2: Not shown in title block; Address3: Not shown in title block; Address4: Not shown in title block; DocumentNumber: 1; Revision: Use project parameter SCH_Rev; SheetNumber: 4; SheetTotal: 9; PageSetup: Record=PageOptions¦CenterHorizontal=True¦CenterVertical=True¦PrintScale=0.69¦XCorrection=1.00¦YCorrection=1.00¦PrintKind=0¦BorderSize=5000000¦LeftOffset=0¦BottomOffset=0¦Orientation=2¦PaperLength=1000¦PaperWidth=1000¦Scale=100¦PaperSource=15¦PrintQuality=600¦MediaType=1¦DitherType=10¦PaperKind=Letter¦PrintScaleMode=1
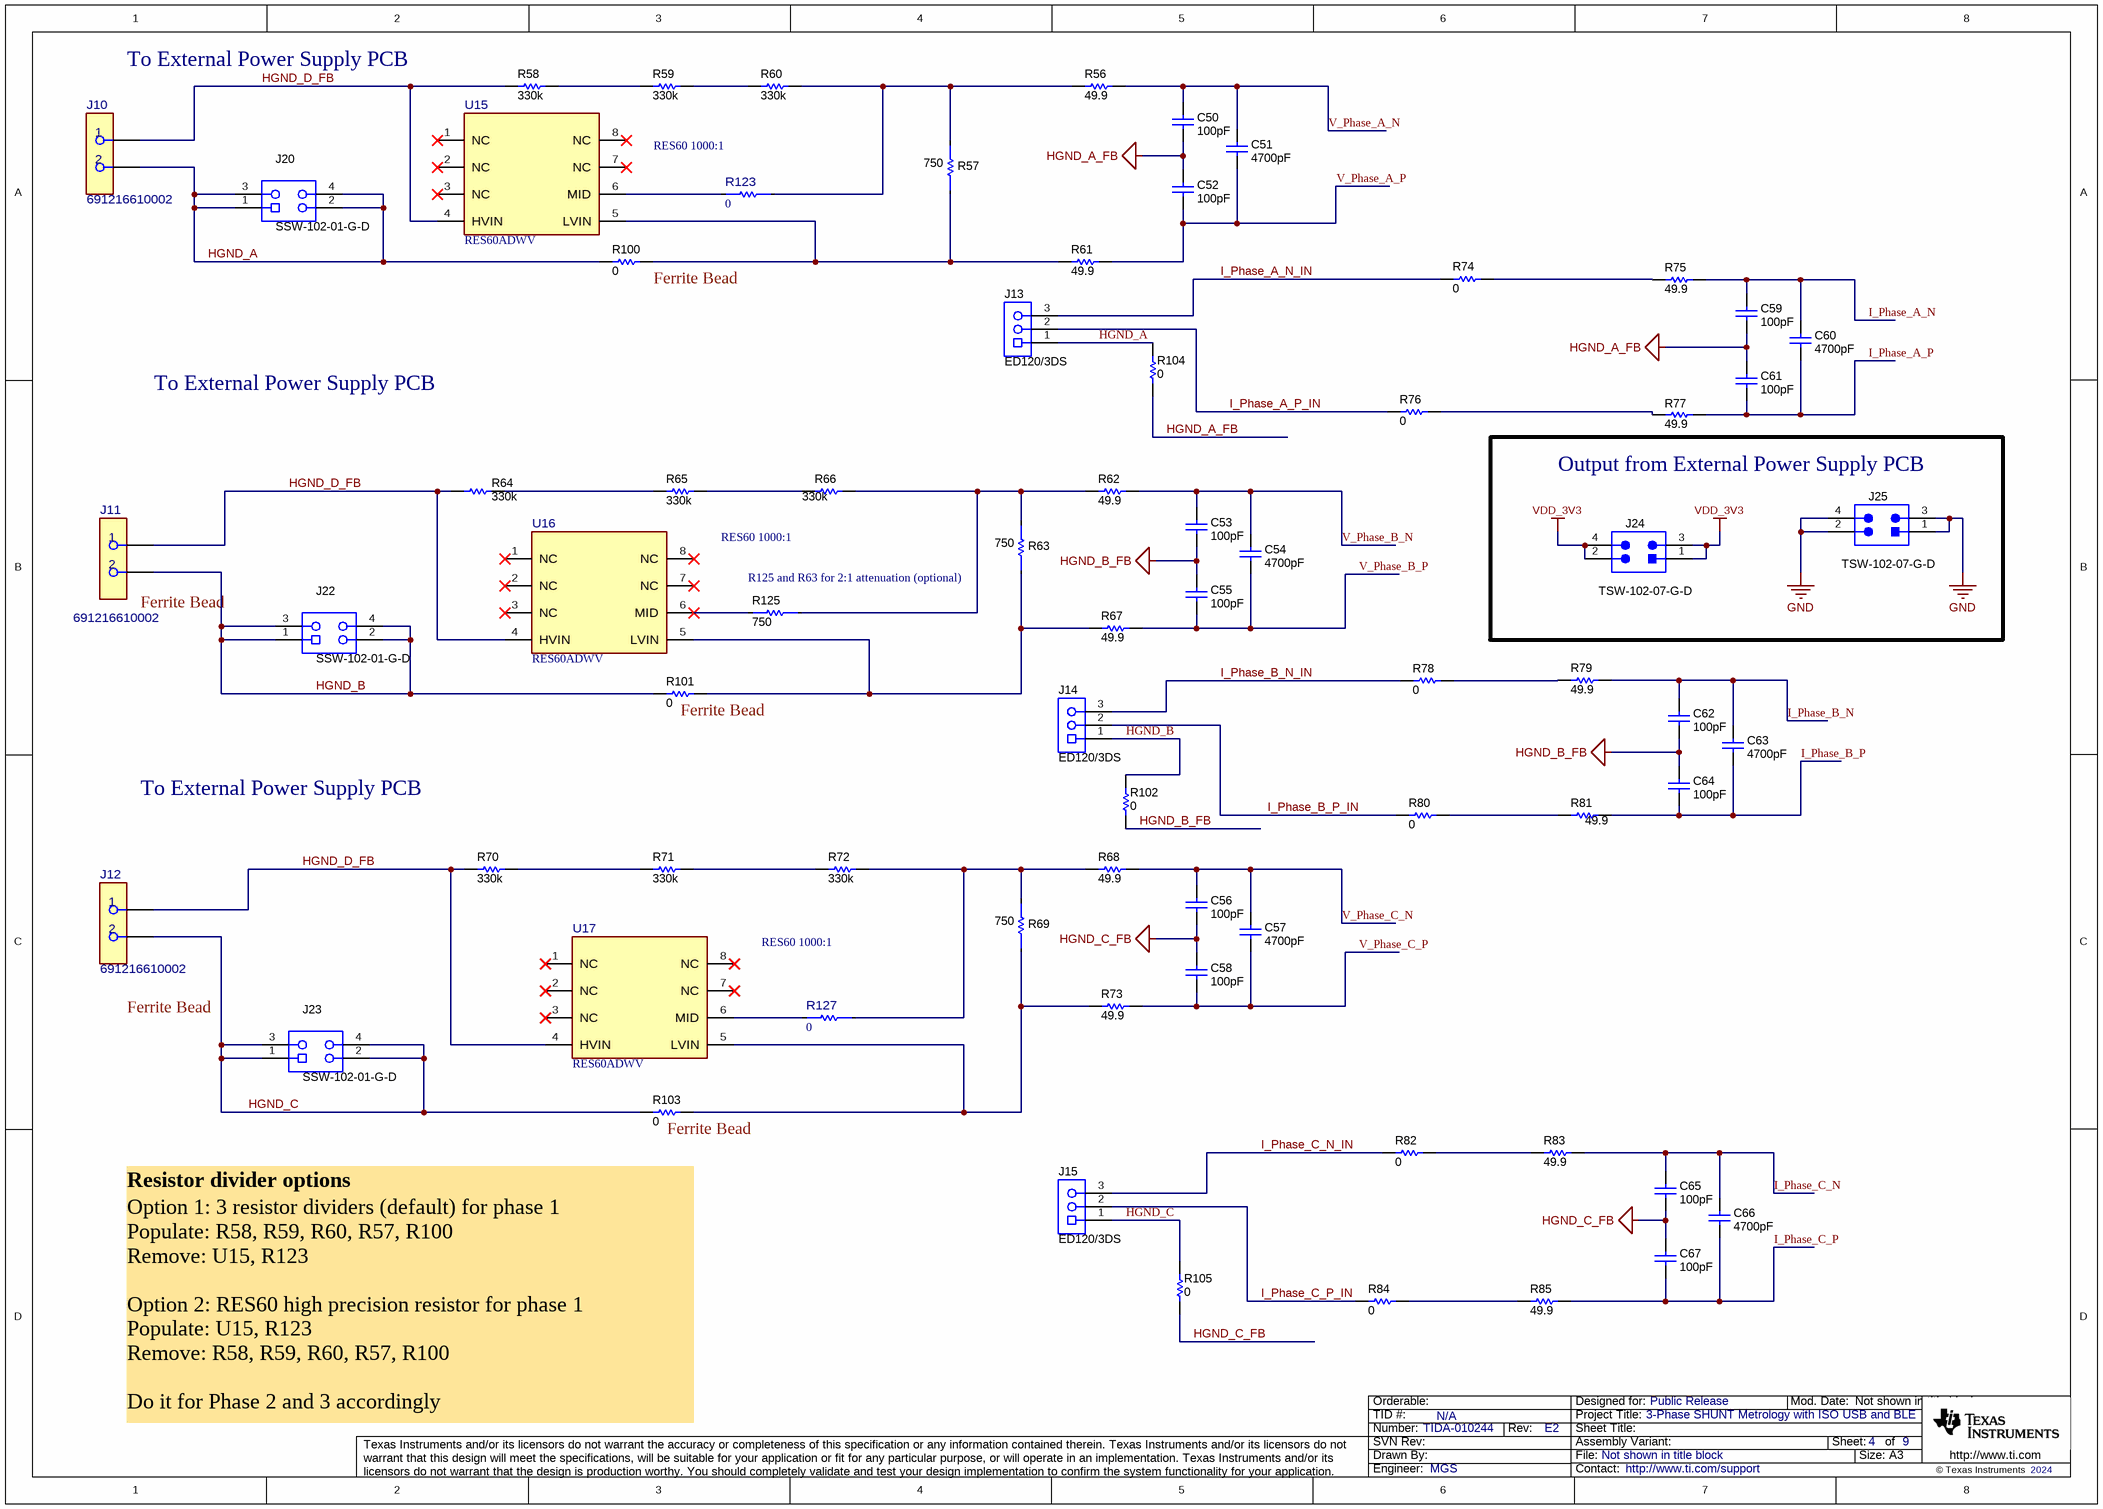
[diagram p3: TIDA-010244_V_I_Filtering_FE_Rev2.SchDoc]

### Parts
C50  ValueDisplayed: 100pF  [0603]  (hidden comment: 885012006057)
C51  ValueDisplayed: 4700pF  [0603]  (hidden comment: C0603C472J1GAC7867)
C52  ValueDisplayed: 100pF  [0603]  (hidden comment: 885012006057)
C53  ValueDisplayed: 100pF  [0603]  (hidden comment: 885012006057)
C54  ValueDisplayed: 4700pF  [0603]  (hidden comment: C0603C472J1GAC7867)
C55  ValueDisplayed: 100pF  [0603]  (hidden comment: 885012006057)
C56  ValueDisplayed: 100pF  [0603]  (hidden comment: 885012006057)
C57  ValueDisplayed: 4700pF  [0603]  (hidden comment: C0603C472J1GAC7867)
C58  ValueDisplayed: 100pF  [0603]  (hidden comment: 885012006057)
C59  ValueDisplayed: 100pF  [0603]  (hidden comment: 885012006057)
C60  ValueDisplayed: 4700pF  [0603]  (hidden comment: C0603C472J1GAC7867)
C61  ValueDisplayed: 100pF  [0603]  (hidden comment: 885012006057)
C62  ValueDisplayed: 100pF  [0603]  (hidden comment: 885012006057)
C63  ValueDisplayed: 4700pF  [0603]  (hidden comment: C0603C472J1GAC7867)
C64  ValueDisplayed: 100pF  [0603]  (hidden comment: 885012006057)
C65  ValueDisplayed: 100pF  [0603]  (hidden comment: 885012006057)
C66  ValueDisplayed: 4700pF  [0603]  (hidden comment: C0603C472J1GAC7867)
C67  ValueDisplayed: 100pF  [0603]  (hidden comment: 885012006057)
J10  691216610002  [FP-691216610002_TERM_BLK_2-MFG]
J11  691216610002  [FP-691216610002_TERM_BLK_2-MFG]
J12  691216610002  [FP-691216610002_TERM_BLK_2-MFG]
J13  ED120/3DS  [On-Shore_ED120_3DS]
J14  ED120/3DS  [On-Shore_ED120_3DS]
J15  ED120/3DS  [On-Shore_ED120_3DS]
J20  SSW-102-01-G-D  [Samtec_SSW-102-01-x-D]
J22  SSW-102-01-G-D  [Samtec_SSW-102-01-x-D]
J23  SSW-102-01-G-D  [Samtec_SSW-102-01-x-D]
J24  TSW-102-07-G-D  [TSW-102-07-G-D]
J25  TSW-102-07-G-D  [TSW-102-07-G-D]
R56  ValueDisplayed: 49.9  [0603]  (hidden comment: CRCW060349R9FKEA)
R57  Res_ohm: 750  [FP-RT0603DRD07750RL_0603-MFG]  (hidden comment: RT0603DRD07750RL)
R58  ValueDisplayed: 330k  [1206]  (hidden comment: CRCW1206330KJNEA)
R59  ValueDisplayed: 330k  [1206]  (hidden comment: CRCW1206330KJNEA)
R60  ValueDisplayed: 330k  [1206]  (hidden comment: CRCW1206330KJNEA)
R61  ValueDisplayed: 49.9  [0603]  (hidden comment: CRCW060349R9FKEA)
R62  ValueDisplayed: 49.9  [0603]  (hidden comment: CRCW060349R9FKEA)
R63  Res_ohm: 750  [FP-RT0603DRD07750RL_0603-MFG]  (hidden comment: RT0603DRD07750RL)
R64  ValueDisplayed: 330k  [1206]  (hidden comment: CRCW1206330KJNEA)
R65  ValueDisplayed: 330k  [1206]  (hidden comment: CRCW1206330KJNEA)
R66  ValueDisplayed: 330k  [1206]  (hidden comment: CRCW1206330KJNEA)
R67  ValueDisplayed: 49.9  [0603]  (hidden comment: CRCW060349R9FKEA)
R68  ValueDisplayed: 49.9  [0603]  (hidden comment: CRCW060349R9FKEA)
R69  Res_ohm: 750  [FP-RT0603DRD07750RL_0603-MFG]  (hidden comment: RT0603DRD07750RL)
R70  ValueDisplayed: 330k  [1206]  (hidden comment: CRCW1206330KJNEA)
R71  ValueDisplayed: 330k  [1206]  (hidden comment: CRCW1206330KJNEA)
R72  ValueDisplayed: 330k  [1206]  (hidden comment: CRCW1206330KJNEA)
R73  ValueDisplayed: 49.9  [0603]  (hidden comment: CRCW060349R9FKEA)
R74  ValueDisplayed: 0  [0603]  (hidden comment: RC0603JR-070RL)
R75  ValueDisplayed: 49.9  [0603]  (hidden comment: CRCW060349R9FKEA)
R76  ValueDisplayed: 0  [0603]  (hidden comment: RC0603JR-070RL)
R77  ValueDisplayed: 49.9  [0603]  (hidden comment: CRCW060349R9FKEA)
R78  ValueDisplayed: 0  [0603]  (hidden comment: RC0603JR-070RL)
R79  ValueDisplayed: 49.9  [0603]  (hidden comment: CRCW060349R9FKEA)
R80  ValueDisplayed: 0  [0603]  (hidden comment: RC0603JR-070RL)
R81  ValueDisplayed: 49.9  [0603]  (hidden comment: CRCW060349R9FKEA)
R82  ValueDisplayed: 0  [0603]  (hidden comment: RC0603JR-070RL)
R83  ValueDisplayed: 49.9  [0603]  (hidden comment: CRCW060349R9FKEA)
R84  ValueDisplayed: 0  [0603]  (hidden comment: RC0603JR-070RL)
R85  ValueDisplayed: 49.9  [0603]  (hidden comment: CRCW060349R9FKEA)
R100  ValueDisplayed: 0  [0603]  (hidden comment: RC0603JR-070RL)
R101  ValueDisplayed: 0  [0603]  (hidden comment: RC0603JR-070RL)
R102  ValueDisplayed: 0  [0603]  (hidden comment: RC0603JR-070RL)
R103  ValueDisplayed: 0  [0603]  (hidden comment: RC0603JR-070RL)
R104  ValueDisplayed: 0  [0603]  (hidden comment: RC0603JR-070RL)
R105  ValueDisplayed: 0  [0603]  (hidden comment: RC0603JR-070RL)
R123  Res_ohm: 0  [FP-CR160000F_0603-MFG]  (hidden comment: CR160000F)
R125  Res_ohm: 750  [FP-RT0603DRD07750RL_0603-MFG]  (hidden comment: RT0603DRD07750RL)
R127  Res_ohm: 0  [FP-CR160000F_0603-MFG]  (hidden comment: CR160000F)
U15  RES60ADWV  [DWV0008A-MFG]
U16  RES60ADWV  [DWV0008A-MFG]
U17  RES60ADWV  [DWV0008A-MFG]

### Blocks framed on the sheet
Output from External Power Supply PCB: J24 J25

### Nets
GND: J25.1 J25.2 J25.3 J25.4
HGND_A_FB: C50.2 C52.1 C59.2 C61.1 R104.1
HGND_B_FB: C53.2 C55.1 C62.2 C64.1 R102.1
HGND_C_FB: C56.2 C58.1 C65.2 C67.1 R105.1
HGND_D_FB: J10.1 J11.1 J12.1 R58.2 R64.2 R70.2 U15.4(HVIN) U16.4(HVIN) U17.4(HVIN)
VDD_3V3: J24.1 J24.2 J24.3 J24.4
HGND_A: J10.2 J13.1 J20.1 J20.2 J20.3 J20.4 R100.1 R104.2
HGND_B: J11.2 J14.1 J22.1 J22.2 J22.3 J22.4 R101.1 R102.2
HGND_C: J12.2 J15.1 J23.1 J23.2 J23.3 J23.4 R103.1 R105.2
I_Phase_A_N: C59.1 C60.1 R75.2
I_Phase_A_N_IN: J13.3 R74.1
I_Phase_A_P: C60.2 C61.2 R77.2
I_Phase_A_P_IN: J13.2 R76.1
I_Phase_B_N: C62.1 C63.1 R79.2
I_Phase_B_N_IN: J14.3 R78.1
I_Phase_B_P: C63.2 C64.2 R81.2
I_Phase_B_P_IN: J14.2 R80.1
I_Phase_C_N: C65.1 C66.1 R83.2
I_Phase_C_N_IN: J15.3 R82.1
I_Phase_C_P: C66.2 C67.2 R85.2
I_Phase_C_P_IN: J15.2 R84.1
V_Phase_A_N: C50.1 C51.1 R56.2
V_Phase_A_P: C51.2 C52.2 R61.2
V_Phase_B_N: C53.1 C54.1 R62.2
V_Phase_B_P: C54.2 C55.2 R67.2
V_Phase_C_N: C56.1 C57.1 R68.2
V_Phase_C_P: C57.2 C58.2 R73.2
NetR56_1: R56.1 R57.2 R60.1 R123.1
NetR57_1: R57.1 R61.1 R100.2 U15.5(LVIN)
NetR58_1: R58.1 R59.2
NetR59_1: R59.1 R60.2
NetR62_1: R62.1 R63.2 R66.1 R125.1
NetR63_1: R63.1 R67.1 R101.2 U16.5(LVIN)
NetR64_1: R64.1 R65.2
NetR65_1: R65.1 R66.2
NetR68_1: R68.1 R69.2 R72.1 R127.1
NetR69_1: R69.1 R73.1 R103.2 U17.5(LVIN)
NetR70_1: R70.1 R71.2
NetR71_1: R71.1 R72.2
NetR74_2: R74.2 R75.1
NetR76_2: R76.2 R77.1
NetR78_2: R78.2 R79.1
NetR80_2: R80.2 R81.1
NetR82_2: R82.2 R83.1
NetR84_2: R84.2 R85.1
NetR123_2: R123.2 U15.6(MID)
NetR125_2: R125.2 U16.6(MID)
NetR127_2: R127.2 U17.6(MID)

Not connected (* = marked no-connect by the designer): U15 1(NC)* 2(NC)* 3(NC)* 7(NC)* 8(NC)*; U16 1(NC)* 2(NC)* 3(NC)* 7(NC)* 8(NC)*; U17 1(NC)* 2(NC)* 3(NC)* 7(NC)* 8(NC)*

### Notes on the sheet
- To External Power Supply PCB
- RES60 1000:1
- (near R100) Ferrite Bead
- (near R63) R125 and R63 for 2:1 attenuation (optional)
- (near J11) Ferrite Bead
- (near R101) Ferrite Bead
- Ferrite Bead
- Resistor divider options
- (near R103) Ferrite Bead
- Option 1: 3 resistor dividers (default) for phase 1
  Populate: R58, R59, R60, R57, R100
  Remove: U15, R123
  Option 2: RES60 high precision resistor for phase 1
  Populate: U15, R123
  Remove: R58, R59, R60, R57, R100
  Do it for Phase 2 and 3 accordingly

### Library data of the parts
C50 C52 C53 C55 C56 C58 C59 C61 C62 C64 C65 C67 = CMP-0006822-4: CAP, CERM, 100 pF, 50 V, +/- 5%, C0G/NP0, 0603; Manufacturer: Wurth Elektronik; TaMin_C: -55°C; Polarized: N; SizeAreaWB_mm2: 4.68; Value1: Unknown; U/M: EA; Value: 100pF; TaMax_C: 125°C; SizeZ_mm: 1; SizeX_mm: 1.6; SizeY_mm: 0.8; Value2: 50V; SizeArea_mm2: 1.28; AEC Category: Q200
C51 C54 C57 C60 C63 C66 = CMP-0006941-4: CAP, CERM, 4700 pF, 100 V, +/- 5%, C0G/NP0, 0603; Manufacturer: Kemet; TaMin_C: -55°C; Polarized: N; SizeAreaWB_mm2: 4.68; Value1: Unknown; U/M: EA; Value: 4700pF; TaMax_C: 125°C; SizeZ_mm: 1; SizeX_mm: 1.6; SizeY_mm: 0.8; Value2: 100V; SizeArea_mm2: 1.28; Cap_F: 4.7nF; AEC Category: Q200
J10-J12 = CMP-0109233-1: 2 Position Wire to Board Terminal Block Horizontal with Board 0.400" (10.16mm) Through Hole; Manufacturer: Wurth Electronics; Current_A: 14A; Max Wire Gauge: 12; SizeZ_mm: 13.9mm; Conn Gender: Female; Min Wire Gauge: 30; Is Female: yes; Row_Count: 1; AEC Qualified: No; ContactFinish: Nickel; Voltage_V: 300V
J13-J15 = CMP-0074911-1: Terminal Block, 5.08 mm, 3x1, Brass, TH; Manufacturer: On-Shore Technology; Cert_VDE: Y; CNHeader: False; Current_A: 15A; Green_Lifecycle: Not Set; Shrouded: N; Gender: Female; Green_REACh: Incomplete; Voltage_V: 300V; Row_Count: 1; Pitch_mm: 5.08; CT: True
J20 J22 J23 = CMP-0055713-1: Receptacle, 2.54mm, 2x2, Gold, TH; Manufacturer: Samtec; Current_A: 4.7A; Voltage_V: 465V; Row_Count: 2; CNHeader: FALSE; Gender: Female; CompType: Socket Strip; RowSpacing_mm: 2.54; CT: TRUE; Cert_UL: Y
J24 J25 = CMP-0075404-1: Header, 100mil, 2x2, Gold, TH; Manufacturer: Samtec; Current_A: 6.3A; Voltage_V: 550V; Row_Count: 2; CNHeader: True; Shrouded: N; Gender: Male; RowSpacing_mm: 2.54; CT: False; Cert_UL: Y; Green_Lifecycle: Active; Green_REACh: Passed
R56 R61 R62 R67 R68 R73 = CMP-0022448-2: RES, 49.9, 1%, 0.1 W, 0603; Manufacturer: Vishay-Dale; Power_W: 100mW; TempCo: 100 ppm/C; Value_Code: 49R9; U/M: EA; Value: 49.9; EIA_Code: E96; SizeX_mm: 1.6; SizeY_mm: 0.8; SizeZ_mm: 1; Value2: 0.1W; SizeArea_mm2: 1.28; VDC_V: 75V; AEC Category: Q200
R57 R63 R69 R125 = CMP-0088453-2: 750 Ohms ±0.5% 0.1W, 1/10W Chip Resistor 0603 (1608 Metric)  Thin Film; Manufacturer: Yageo; VDC_V: 75V; AEC Qualified: No; SizeZ_mm: 0.55mm; TempCo: 25ppm/°C; Power_W: 100mW
R58-R60 R64-R66 R70-R72 = CMP-0018656-3: RES, 330 k, 5%, 0.25 W, AEC-Q200 Grade 0, 1206; Manufacturer: Vishay-Dale; Power_W: 250mW; TempCo: 200 ppm/C; Value: 330k; EIA_Code: E24; SizeX_mm: 3.2; SizeY_mm: 1.6; SizeZ_mm: 1.35; Value2: 0.25W; SizeArea_mm2: 5.12; AEC Qualified: Y; VDC_V: 200V; AEC Category: Q200; AEC Grade: 0
R74 R76 R78 R80 R82 R84 R100-R105 = CMP-0025885-5: RES, 0, 5%, 0.1 W, 0603; Manufacturer: Yageo; Power_W: 100mW; TempCo: 200 ppm/C; Value_Code: 0000; Value: 0; EIA_Code: E24; SizeX_mm: 1.6; SizeZ_mm: 1; Value2: 0.1W; SizeArea_mm2: 1.28; CompType: Resistor; AEC Qualified: N; VDC_V: 75V; AEC Category: Q200; SizeY_mm: 0.8; SizeAreaWB_mm2: 4.68
R75 R77 R79 R81 R83 R85 = CMP-0022448-4: RES, 49.9, 1%, 0.1 W, AEC-Q200 Grade 0, 0603; Manufacturer: Vishay-Dale; Power_W: 100mW; TempCo: 100 ppm/C; Value_Code: 49R9; Value: 49.9; EIA_Code: E96; SizeX_mm: 1.6; SizeY_mm: 0.8; SizeZ_mm: 1; Value2: 0.1W; SizeArea_mm2: 1.28; AEC Qualified: Y; VDC_V: 75V; AEC Category: Q200; AEC Grade: 0
R123 R127 = CMP-0097819-1: 0 Ohms ±1% Chip Resistor 0603 (1608 Metric) Thick Film; Manufacturer: Meritek Electronics; AEC Qualified: No; SizeZ_mm: 0.55mm; Value: 0; VDC_V: 75V; Power_W: 100mW; Max Current: 2A
U15-U17 = CMP-0121043-1: Manufacturer: Texas Instruments; SizeZ_mm: 2.8mm; AEC Qualified: No; Standoff Height: 0.36mm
